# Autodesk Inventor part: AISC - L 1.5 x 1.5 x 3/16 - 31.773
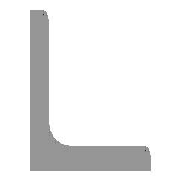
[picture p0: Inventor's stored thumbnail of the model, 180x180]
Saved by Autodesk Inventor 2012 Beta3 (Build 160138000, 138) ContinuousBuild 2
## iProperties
IsCustomPart: 1
Created: 2010-11
Part Number: AISC - L 1.5 x 1.5 x 3/16 - 31.773
Material: Steel, Mild
Description: Angle Steel
Document SubType Name: Modeling
Standard: ANSI
Designer: Beta-8540w
Standards Organization: ANSI
Language: en-US
Size Designation: L 1.5 x 1.5 x 3/16
Categories: <MemberInstance><Categories><Category DisplayName="Structural Shapes" InternalName="089c4875-fa83-4c05-b084-43b9cc11f5ed" Mnemonic="GRDR"><CategoryParameter Dis
Stock Number: L 1.5 x 1.5 x 3/16
Density: 7.86 g/cm^3
_CCFamilyMember: 5
_CCFamilyDisplayName: ANSI L (Equal angles) - Angle Steel
_FrameMemberDoc: Frame Member File
_Version: 15.0.0
_GetPNFromCC: 1
G_L: 31.773 in
G_W: 1.500 in
G_H: 1.500 in
+5968F0EF-F5AD-46F6-A5DD-B649BA20EEC9+CUTDETAIL1: Cut
Author: Beta-8540w
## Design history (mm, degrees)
node "Start plane"
node "End plane"
sketch "Sketch"
  geometry: L1 (38.1, 0)-(0, 0); L2 (0, 0)-(0, 38.1); L3 (0, 38.1)-(2.476, 38.1); L4 (4.762, 35.814)-(4.762, 9.589); L5 (9.588, 4.763)-(35.814, 4.763); L6 (38.1, 2.477)-(38.1, 0); L7 (0, -11.041)-(0, 31.538); L8 (-11.041, 0)-(31.538, 0); L9 (0, 48.496)-(0, -20.964) reference; L10 (-20.964, 0)-(48.496, 0) reference; A1 r 4.826 centre (9.588, 9.589) between (4.762, 9.589) and (9.588, 4.763); A2 r 2.286 centre (2.476, 35.814) between (4.762, 35.814) and (2.476, 38.1); A3 r 2.286 centre (35.814, 2.477) between (38.1, 2.477) and (35.814, 4.763); 3 further points
  constraints: 16 end point, 6 point on circle, 6 point on line, 6 tangent, 4 parallel, 3 centre point, 2 collinear, 1 equal radius, 1 horizontal, 1 perpendicular
  dimensions: "d0" = 38.1 distance between parallel lines of L6 L2 (= G_H); "d1" = 38.1 distance between parallel lines of L3 L1 (= G_H); "d2" = 4.7625 distance between parallel lines of L2 L4 (= G_T); "d3" = 4.7625 distance between parallel lines of L1 L5 (= G_T); "d10" = 0 distance between parallel lines of L7 L2 (computed from ex); "d11" = 0 distance between parallel lines of L8 L1 (computed from d10); "d14" = 4.826 radius of A1 (= G_IR); "d15" = 2.286 radius of A2 (= G_ER)
extrude "Body" new body sketch "Sketch" stored distance "d4" = 807.0404 (= G_L); taper "d5" = 0 deg
node "Driven Length"
  sketch "Sketch3"
    geometry: L1 (0, 0)-(10, 0) reference
    constraints: 2 end point, 1 horizontal
  workplane "Work Plane3"
  sketch "Sketch4"
    geometry: L1 (-2, 0)-(12, 0) reference; L2 (-2, 807.04)-(12, 807.04) reference
    dimensions: "d17" = 807.0404 distance between parallel lines of L1 L2 (derived)
workplane "Work Plane4"
split "Split1"
body "Solid1"
other parameters: "G_H" = 38.1 [user parameter; used in 2 equation terms], "G_T" = 4.7625 [user parameter; used in 2 equation terms], "G_ER" = 2.286 [user parameter; used in 1 equation term], "G_IR" = 4.826 [user parameter; used in 1 equation term], "G_L" = 807.0404 (= d17) [user parameter; used in 1 equation term], "ex" = 0 [user parameter; used in 1 equation term], "G_OFFSET_START" = 0 [user parameter; used in 1 equation term], "G_OFFSET_END" = -29.72503 [user parameter; used in 1 equation term], "d12" = 0 (computed from G_OFFSET_START), "d13" = 807.0404 (= G_OFFSET_END + B_L), "B_L" = 836.76542 [user parameter; used in 1 equation term], "d16" = 90 deg, "MAS" = 0.26787 [user parameter]
